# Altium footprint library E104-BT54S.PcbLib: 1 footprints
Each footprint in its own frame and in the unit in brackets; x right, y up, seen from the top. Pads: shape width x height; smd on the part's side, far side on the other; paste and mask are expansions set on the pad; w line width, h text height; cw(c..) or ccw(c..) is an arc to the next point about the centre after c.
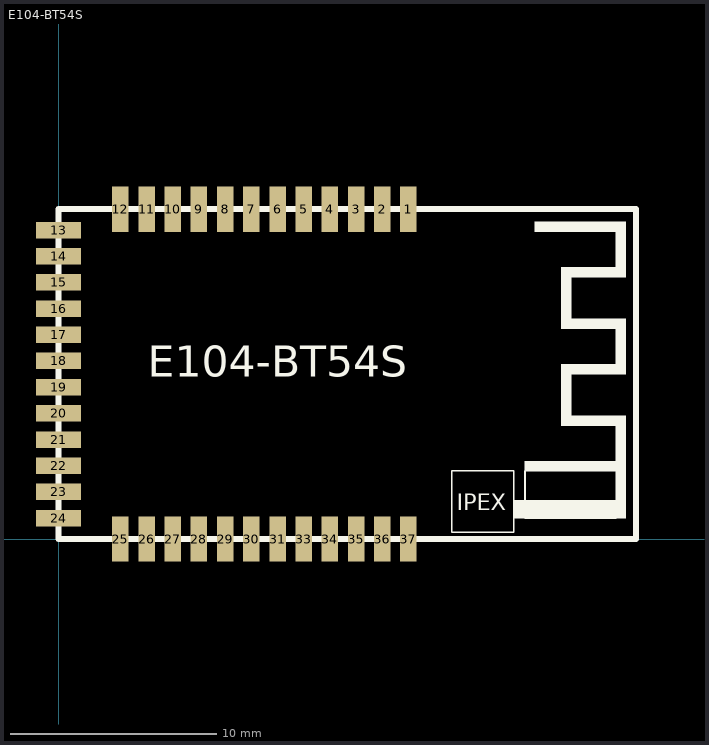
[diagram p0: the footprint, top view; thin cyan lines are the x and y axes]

## E104-BT54S [mm]
pads (36):
  rect 0.8x2.2 smd: 1(16.97,16) 2(15.7,16) 3(14.43,16) 4(13.16,16) 5(11.89,16) 6(10.62,16) 7(9.35,16) 8(8.08,16) 9(6.81,16) 10(5.54,16) 11(4.27,16) 12(3,16) 25(3,0) 26(4.27,0) 27(5.54,0) 28(6.81,0) 29(8.08,0) 30(9.35,0) 31(10.62,0) 33(11.89,0) 34(13.16,0) 35(14.43,0) 36(15.7,0) 37(16.97,0)
  rect 2.2x0.8 smd: 13(0,14.985) 14(0,13.715) 15(0,12.445) 16(0,11.175) 17(0,9.905) 18(0,8.635) 19(0,7.365) 20(0,6.095) 21(0,4.825) 22(0,3.555) 23(0,2.285) 24(0,1.015)
Top Overlay:
  region: 22.611,0.986 22.611,1.888 22.114,1.888 22.114,0.986
  region: 27.049,0.983 27.049,1.883 22.606,1.883 22.606,0.983
  region: 27.51,12.687 27.51,15.387 27.01,15.387 27.01,12.687
  region: 27.01,10.185 27.01,10.685 24.37,10.685 24.37,10.185
  region: 27.509,7.986 27.509,10.686 27.009,10.686 27.009,7.986
  region: 27.012,7.987 27.012,8.487 24.372,8.487 24.372,7.987
  region: 24.87,5.978 24.87,8.024 24.363,8.024 24.363,5.978
  region: 27.041,5.489 27.041,5.986 24.363,5.986 24.363,5.489
  region: 27.008,3.284 27.008,3.784 22.608,3.784 22.608,3.284
  region: 27.509,0.986 27.509,5.986 27.009,5.986 27.009,0.986
  region: 24.869,10.685 24.869,12.738 24.369,12.738 24.369,10.685
  region: 27.012,12.687 27.012,13.187 24.372,13.187 24.372,12.687
  region: 23.071,15.387 23.071,14.887 27.011,14.887 27.011,15.387
  lines w0.076: 19.074,0.319 22.074,0.319 22.074,3.319 19.074,3.319 19.074,0.319
  lines w0.1: 22.613,1.887 22.613,3.287
  lines w0.3: 0,0 0,16 28,16 28,0 0,0
  text "IPEX" at 19.304,1.397 h0.8
  text "E104-BT54S" at 4.318,7.874 h1.5
3D body "IPEX-RF.STEP": height 1.25, standoff -0.03, extent 19.034,0.5 22.034,3.35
